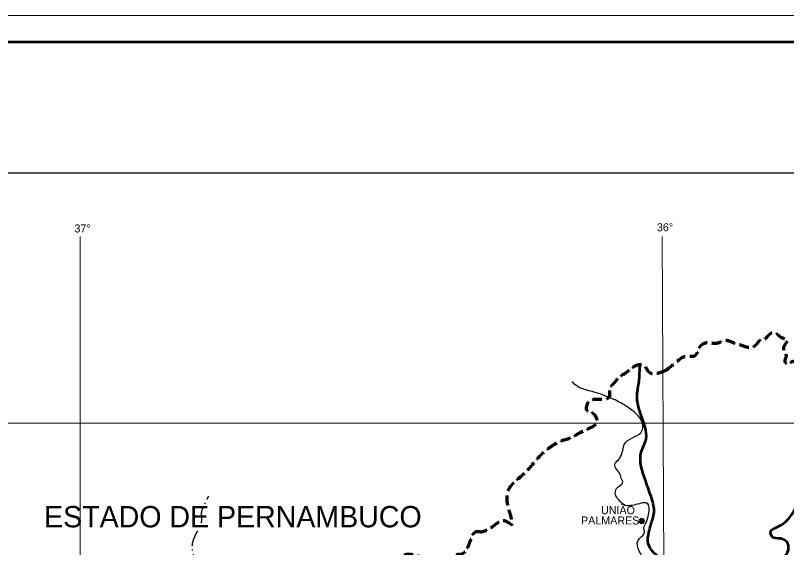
# Model space of a CAD drawing. Extents: x 512883 to 1063249, y 8784064 to 9081064.
# Drawn here: x 707317 to 851806, y 8981350 to 9081064 of the extents above; entities that cross this region are included whole.
import ezdxf

# ---------------------------------------------------------------- set-up
doc = ezdxf.new("R2010")
doc.units = 0
doc.header["$LTSCALE"] = 600
doc.linetypes.add('DOT_DASHED', pattern=[7.7, 5, -1.2, 0.3, -1.2])
doc.linetypes.add('MEDIUM_DASHED', pattern=[4.5, 3, -1.5])
for name, color, linetype, lineweight in [('1', 7, 'Continuous', 25), ('10', 7, 'Continuous', 53), ('13', 7, 'Continuous', 90), ('3', 7, 'Continuous', 25), ('4', 7, 'Continuous', 13), ('5', 7, 'Continuous', 13), ('60', 7, 'Continuous', 25)]:
    doc.layers.add(name, color=color, linetype=linetype, lineweight=lineweight)
doc.layers.add('11', color=7, linetype='Continuous')

msp = doc.modelspace()

# ---------------------------------------------------------------- linework, layer by layer
at = {"layer": '1', "lineweight": 13}
for p, q in [((719468, 8831691.5), (719468, 9039622)), ((828480.7, 9039622), (829566.9, 8831691.5)), ((583128.5, 9004643.8), (934661.1, 9004629.5))]:
    msp.add_line(p, q, dxfattribs=at)
for points in [[(512883.1, 8784063.9), (1063248.6, 8784063.9), (1063248.6, 9081063.9), (512883.1, 9081063.9)], [(537883.1, 9076063.9), (1058248.6, 9076063.9), (1058248.6, 8789063.9), (537883.1, 8789063.9)]]:
    msp.add_lwpolyline(points, close=True, dxfattribs=at)
at = {"layer": '1', "lineweight": 53}
msp.add_lwpolyline([(537883.1, 8789063.9), (1058248.6, 8789063.9), (1058248.6, 9076063.9), (537883.1, 9076063.9)], close=True, dxfattribs=at)
at = {"layer": '1'}
for points in [[(537883.1, 9076063.9), (1058248.6, 9076063.9), (1058248.6, 8789063.9), (537883.1, 8789063.9)], [(566926, 9051542.3), (945407.2, 9051542.3), (945407.2, 8818457.9), (566926, 8818457.9)]]:
    msp.add_lwpolyline(points, close=True, dxfattribs=at)
at = {"layer": '10'}
for points in [[(825438.5, 8993772), (824583.7, 8999244.2), (825480.7, 9001730.5), (825295.9, 9003900.2), (824235.6, 9007089.6), (823785.3, 9009634.1), (824118.9, 9012181.1), (824311.4, 9014769.4), (824362.2, 9015625.2)], [(845019.7, 8956739.4), (846265.2, 8957911.5), (847406.7, 8960106.4), (847421.5, 8962401.9), (846655.5, 8964423.7), (846728.2, 8966928.1), (847611.9, 8968809.1), (848345.1, 8971566.1), (849038.1, 8972507.4), (851008.9, 8974225), (852678.9, 8975879), (853028.9, 8976944.4), (852030.2, 8978193.3), (851496.1, 8979235), (852140.4, 8980948.2), (851842.9, 8982408.1), (850670.3, 8983030.3), (849119.1, 8983359.2), (848846, 8984422.6), (849983.5, 8985156.7), (854563.6, 8990826.8), (856059.2, 8993711.5), (857398.3, 8996199.1), (858506.1, 8997809.6), (860401.3, 8999088.7), (864451.3, 9003709.9)], [(846608.8, 8964716.3), (843344.4, 8965769.4), (839632, 8967051.3), (837264.2, 8968525.3), (835285.3, 8971169.2), (834075.1, 8973377.3), (832001.8, 8975478.3), (830189, 8977642.8), (828585.8, 8979035.8), (826881.9, 8980449.3), (825898.7, 8982115.6), (826015.6, 8984265.4), (826401.6, 8985706.6), (826979.7, 8987962.2), (826549.3, 8990527.6), (825448.5, 8993737.8), (825438.5, 8993772)]]:
    msp.add_spline(points, degree=3, dxfattribs=at)
at = {"layer": '13', "linetype": 'MEDIUM_DASHED', "lineweight": 70}
for points in [[(829197.7, 9014555.7), (831473.6, 9016400), (832666.2, 9017154.5), (834733.9, 9017369.9), (835640, 9019042.3), (836236.9, 9019586.8), (837561.8, 9019737.1), (838427.1, 9019635.6), (839749.4, 9020015.5), (840270.1, 9020184.1), (841903.2, 9019730.3), (843435.9, 9019255.3), (844202.6, 9018986.5), (845489.1, 9018969.8), (846564, 9019912.3), (847141.3, 9020415), (847503.1, 9020416.2), (848201.5, 9020877.5), (849137.8, 9021631.8), (849378.7, 9021653.5), (851009.8, 9020657.6), (851917.3, 9020333.2), (851204.2, 9018711.4), (851722.8, 9017284.2), (851463.5, 9016311.1), (851528.3, 9016051.6), (853343.4, 9016311.1), (853862, 9014494.6), (854510.2, 9013456.6), (856519.7, 9014819), (859436.7, 9015467.7), (863390.8, 9016246.2), (864298.3, 9017478.8), (865141, 9018062.7), (866956, 9018906), (870290.9, 9020619.3), (871354.3, 9021775.5), (873540.1, 9022444.2), (874876.6, 9023632.2), (878429.5, 9024355.4), (880633.5, 9024420.3), (881745.7, 9023840.8), (883985, 9024525.5), (884931.5, 9022281.3), (886399.3, 9021809.7), (890479.7, 9020270.3), (891416.2, 9021016.7), (892059.7, 9021678.2)], [(829197.7, 9014555.7), (827054.4, 9013901.8), (826188.3, 9014066), (825249.8, 9015335.9), (823860.9, 9015519.2), (821666.3, 9014051.3), (820229.6, 9013107.6), (819575.4, 9012291.7), (818644.2, 9011078.3), (818441.8, 9009387.3), (817941.4, 9009197.9), (816153.7, 9009108.6), (814711, 9008707.5), (814318.7, 9007829.7), (814265.1, 9007224.4), (815276.2, 9006664.2), (816131.5, 9005665.3), (816241.4, 9004810), (814647, 9003594.5), (813007.7, 9002796.2), (810909.4, 9001704.3), (809286.8, 9001219.1), (808467.6, 9000778.2)], [(808467.6, 9000778.2), (806334.2, 8999227), (802819.1, 8995396.8), (800888.6, 8993679.3), (799718.5, 8992256.5), (799378.2, 8990314.7), (799886.6, 8987958.2), (800159, 8986957.4), (800295.5, 8985517.9)], [(800290, 8985576.4), (798848.1, 8986353.2), (796511, 8985099.3), (795081.6, 8984368.4), (794561.3, 8984247.3)], [(794561.3, 8984247.3), (793616.3, 8984286), (792392.4, 8982278.7), (790528.1, 8980018.9), (790126.1, 8980017.6), (788955.1, 8978678.2), (787269.9, 8978401.5), (785639, 8978667.5), (783741.9, 8979370.9), (781684.8, 8980011.2), (780098.6, 8979860), (778786.9, 8978520.2), (777001.7, 8978201.4), (775996.1, 8978260.7), (775361.7, 8977465.7), (775246.4, 8976985.3), (773727.5, 8974392.8), (772648.9, 8973784.1), (770940.2, 8973820.3), (769920, 8973378.8), (768383.8, 8972351.3), (766882.2, 8971824.7), (766821.9, 8971824.5)]]:
    msp.add_spline(points, degree=3, dxfattribs=at)
at = {"layer": '3'}
msp.add_lwpolyline([(537883.1, 9076063.9), (1058248.6, 9076063.9), (1058248.6, 8789063.9), (537883.1, 8789063.9)], close=True, dxfattribs=at)
at = {"layer": '4', "lineweight": 25}
msp.add_spline([(851191, 8938383.9), (850602.3, 8938925.5), (848994.8, 8938925.2), (848220.2, 8939381.5), (847812, 8939817), (847628.5, 8939941.4), (847524.5, 8940708.9), (847093, 8942140), (847028.6, 8943301.6), (846151.5, 8944027.4), (845661.9, 8944462.9), (845415.3, 8945271.8), (844986.3, 8945873.3), (844821.8, 8946454.1), (845166.1, 8947014.2), (846057.5, 8948383.3), (846522.9, 8949275.3), (846540.5, 8950208.7), (845256.1, 8951058.9), (844764.5, 8952158.2), (844803.5, 8952739), (844921.2, 8954253.2), (844879.4, 8954647.3), (845080.1, 8955601.4), (844874.6, 8956285.9), (844384.1, 8957032.6), (843895.5, 8957094.7), (843548.4, 8957509.5), (842975.9, 8958463.6), (843381, 8959106.6), (843296.9, 8960040), (843904.3, 8961077.2), (844025, 8961575.1), (842717, 8963524.6), (842593.4, 8964043.2), (843142.7, 8964084.7), (841651.6, 8966013.6), (839348.6, 8967278.5), (838208.6, 8967444.2), (835007.4, 8969642.5), (833416.8, 8970824.5), (833231, 8971737.2), (832698.8, 8972815.7), (830252.2, 8974454), (828945.4, 8976009.4), (828332.7, 8976776.8), (827212.5, 8977129.2), (826131.9, 8977875.8), (825008.6, 8979286.1), (824163.5, 8982998.9), (825197.8, 8984202.1), (825073.8, 8984845.1), (825376.3, 8985778.5), (825466.6, 8989740.3), (824246.1, 8989574.2), (822904, 8989262.8), (821581.4, 8989262.6), (820337, 8990341.1), (819744.2, 8991274.4), (819944.3, 8992415.2), (820451.8, 8992850.9), (821120.8, 8993722.2), (820854.7, 8994261.4), (820608.2, 8995049.6), (819605.7, 8996916.2), (820294.9, 8997808.2), (820821.7, 8998596.5), (821628.5, 9001044.2), (824715.2, 9003222.6), (824854.6, 9004280.5), (822383.3, 9007412.2), (820324.4, 9008677.2), (817614.6, 9009859.1), (815944.4, 9010418.9), (811767.4, 9012326.6), (811665.2, 9012471.8)], degree=3, dxfattribs=at)
at = {"layer": '4', "linetype": 'DOT_DASHED', "lineweight": 25}
msp.add_spline([(737771.9, 8973878.1), (738007.4, 8976016.7), (739042.5, 8976929.5), (740383.3, 8977697.2), (740702.9, 8979750.7), (740453.3, 8981596.7), (740956.7, 8983442.9), (741968, 8985558.7), (742250.1, 8986512.9), (742185.8, 8987633), (742689.7, 8989292.4), (743519, 8990993.4)], degree=3, dxfattribs=at)
at = {"layer": '5'}
for p, q in [((824350.6, 8986338.8), (825015.4, 8986338.8)), ((824351.2, 8986308.8), (825015.1, 8986308.8)), ((824352.7, 8986368.8), (825013.3, 8986368.8)), ((824354.2, 8986278.8), (825011.8, 8986278.8)), ((824357.5, 8986398.8), (825008.5, 8986398.8)), ((824360.2, 8986248.8), (825005.8, 8986248.8)), ((824365.6, 8986428.8), (825000.4, 8986428.8)), ((824369.2, 8986218.8), (824996.8, 8986218.8)), ((824376.4, 8986458.8), (824989.6, 8986459.1)), ((824381.8, 8986188.8), (824984.5, 8986189.1)), ((824390.8, 8986488.8), (824975.5, 8986488.8)), ((824397.7, 8986158.8), (824968.3, 8986158.8)), ((824409.1, 8986518.8), (824957.2, 8986518.8)), ((824418.4, 8986128.8), (824947.9, 8986129.1)), ((824433.1, 8986548.8), (824933.5, 8986548.8)), ((824443.6, 8986098.5), (824922.7, 8986098.8)), ((824462.2, 8986578.8), (824903.8, 8986578.8)), ((824476.9, 8986068.8), (824889.1, 8986068.8)), ((824501.8, 8986608.8), (824864.2, 8986608.8)), ((824521.9, 8986038.8), (824844.1, 8986038.8)), ((824559.1, 8986638.8), (824806.9, 8986638.8)), ((824595.7, 8986008.8), (824770, 8986008.8))]:
    msp.add_line(p, q, dxfattribs=at)
for radius in [506.1, 332.9]:
    msp.add_circle((824683.1, 8986329.8), radius, dxfattribs=at)
at = {"layer": '60'}
msp.add_spline([(928828.8, 9027989.5), (927727.3, 9017705.9), (905698.2, 8975836.8), (863108.4, 8926255), (823455.9, 8876673.2), (798489.5, 8846556.8), (787107.7, 8828193.2)], degree=3, dxfattribs=at)
msp.add_spline([(928828.8, 9027989.5), (927727.3, 9017705.9), (905698.2, 8975836.8), (863108.4, 8926255), (823455.9, 8876673.2), (798489.5, 8846556.8), (787107.7, 8828193.2)], degree=3, dxfattribs=at)

# ---------------------------------------------------------------- texts
at = {"layer": '1'}
for s, p in [('36°', (827513.4, 9040618.9)), ('37°', (718375.7, 9040396.2))]:
    msp.add_text(s, height=1500, dxfattribs=at).set_placement(p)
at = {"layer": '11'}
msp.add_text('ESTADO DE PERNAMBUCO', height=4000, dxfattribs=at).set_placement((712696, 8985141))
at = {"layer": '5'}
for s, p in [('UNIÃO', (817042.2, 8987611.1)), ('PALMARES', (813290.7, 8985675.2))]:
    msp.add_text(s, height=1500, dxfattribs=at).set_placement(p)

doc.saveas('drawing.dxf')
